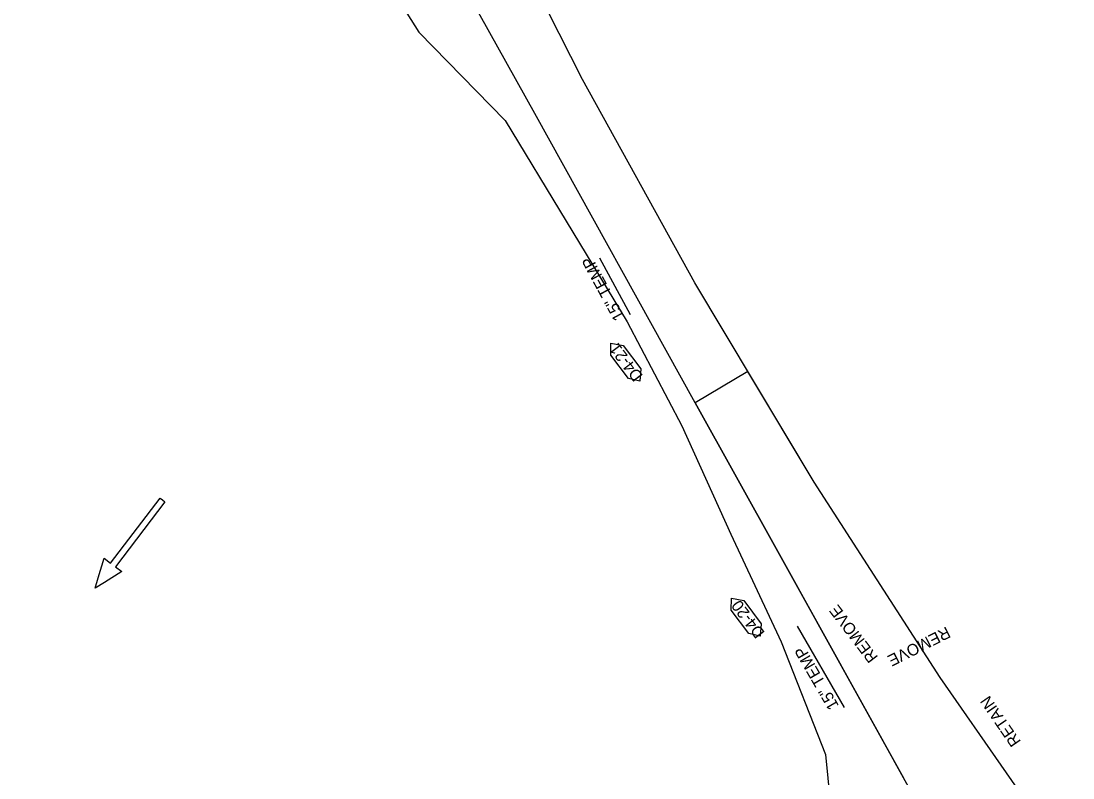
# Model space of a CAD drawing. Extents: x 465700 to 483515, y 488970 to 507540.
# Drawn here: x 475845.7 to 476298.7, y 501161.6 to 501487.4 of the extents above; entities that cross this region are included whole.
import ezdxf

# ---------------------------------------------------------------- set-up
doc = ezdxf.new("R2010")
doc.units = 0
for name, color, linetype in [('Default', 7, 'Continuous'), ('Exist Plan Preparation Drainage Flow Arrows', 7, 'Continuous'), ('Exist Plan Preparation Watershed Blue', 7, 'Continuous'), ('Prop Drainage Structure Box Number Symbol CELL', 7, 'Continuous'), ('Prop Drainage Structure Pipe Collar Label', 7, 'Continuous'), ('Prop Drainage Structure Pipe Side Drain 15in', 7, 'Continuous'), ('Prop Drainage Structure Pipe Side Drain 15in Label', 7, 'Continuous')]:
    doc.layers.add(name, color=color, linetype=linetype)

# ---------------------------------------------------------------- blocks, each defined once
blk = doc.blocks.new('Existing ground flow arrow')
at = {"layer": 'Default'}
blk.add_line((2.5, -4.33), (2.5, -4.33), dxfattribs=at)
blk.add_lwpolyline([(-1.29, -47.2), (-1.28, -12.53), (-4.77, -12.53), (-1.65, -4.33), (0, 0), (1.65, -4.33), (4.78, -12.53), (1.28, -12.52), (1.29, -47.19), (0, -47.2)], close=True, dxfattribs=at)

msp = doc.modelspace()

# ---------------------------------------------------------------- linework, layer by layer
at = {"layer": 'Exist Plan Preparation Watershed Blue'}
for points in [[(476298.67, 501122.89), (476241.47, 501204.91), (476187.17, 501288.88), (476158.71, 501336.62), (476135.95, 501323.05), (476067.03, 501447.55), (475991.45, 501583.03), (475979.89, 501577.6), (475989.75, 501525.93), (475952.06, 501503.83), (475913.25, 501516.29), (475856.62, 501565), (475796.08, 501633.7), (475711.48, 501773.13), (475711.48, 501773.13), (475711.48, 501773.13), (475711.48, 501773.13), (475554.69, 502024.6)], [(476298.67, 501122.89), (476241.47, 501204.91), (476187.17, 501288.88), (476135.85, 501374.69), (476087.55, 501462.25), (476042.34, 501551.45), (476016.26, 501594.46), (475991.45, 501583.03), (475979.89, 501577.6), (475989.75, 501525.93), (475952.06, 501503.83), (475913.25, 501516.29), (475856.62, 501565), (475796.08, 501633.7), (475711.48, 501773.13), (475566.02, 502004.18)], [(476271.01, 501080.04), (476171.6, 501259.06), (476135.95, 501323.05), (476067.03, 501447.55), (475991.45, 501583.03), (475979.89, 501577.6), (475989.75, 501525.93), (476017, 501482.55), (476054.13, 501444.57), (476106.79, 501358), (476130.32, 501313.13), (476151.3, 501266.56), (476173.03, 501220.2), (476192.06, 501171.72), (476197.86, 501113.54)], [(476298.67, 501122.89), (476241.47, 501204.91), (476187.17, 501288.88), (476158.71, 501336.62), (476135.95, 501323.05), (476171.6, 501259.06), (476225.79, 501161.43)]]:
    msp.add_lwpolyline(points, dxfattribs=at)
at = {"layer": 'Prop Drainage Structure Box Number Symbol CELL'}
for points in [[(476107.23, 501333.52), (476099.62, 501343.57), (476099.73, 501348.8), (476104.96, 501347.81), (476112.57, 501337.76), (476112.13, 501332.41), (476107.23, 501333.52)], [(476159.16, 501223.75), (476151.55, 501233.8), (476151.65, 501239.02), (476156.89, 501238.04), (476164.49, 501227.99), (476164.05, 501222.64), (476159.16, 501223.75)]]:
    msp.add_lwpolyline(points, dxfattribs=at)
at = {"layer": 'Prop Drainage Structure Pipe Side Drain 15in'}
for p, q in [((476108.12, 501360.96), (476094.91, 501385.32)), ((476200.37, 501192.01), (476180.08, 501226.97))]:
    msp.add_line(p, q, dxfattribs=at)

# ---------------------------------------------------------------- block references
at = {"layer": 'Exist Plan Preparation Drainage Flow Arrows', "xscale": 1.0124070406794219, "yscale": 1.0124070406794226, "rotation": 142.7346422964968}
msp.add_blockref('Existing ground flow arrow', (475877.69, 501243.26), dxfattribs=at)

# ---------------------------------------------------------------- texts
at = {"layer": 'Prop Drainage Structure Box Number Symbol CELL'}
for s, p in [('D4-21', (476113.71, 501334.73)), ('D4-20', (476166.23, 501224.17))]:
    msp.add_text(s, height=5, rotation=127.1208, dxfattribs=at).set_placement(p)
at = {"layer": 'Prop Drainage Structure Pipe Collar Label'}
for s, rotation, p in [('REMOVE', 127.3506, (476214.96, 501213.63)), ('REMOVE', 206.6713, (476244.25, 501226.94)), ('RETAIN', 124.5075, (476276.43, 501177.27))]:
    msp.add_text(s, height=5, rotation=rotation, dxfattribs=at).set_placement(p)
at = {"layer": 'Prop Drainage Structure Pipe Side Drain 15in Label'}
for rotation, p in [(118.4837, (476105.77, 501360.05)), (120.1314, (476198.03, 501192.71))]:
    msp.add_text('15" TEMP', height=5, rotation=rotation, dxfattribs=at).set_placement(p)

doc.saveas('drawing.dxf')
